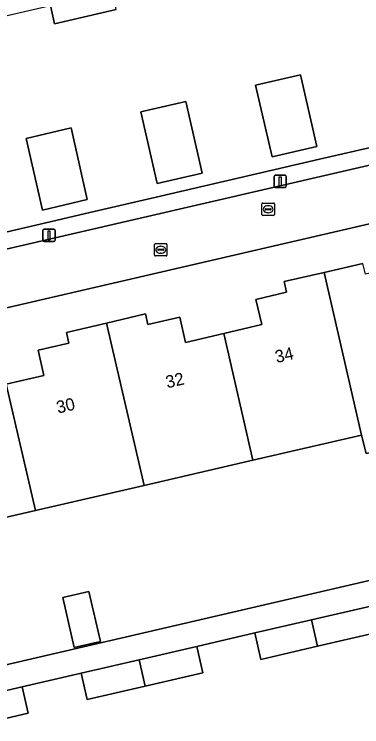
# Model space of a CAD drawing. Extents: x 156412 to 157779, y 382335 to 383768.
# Drawn here: x 156851.9 to 156880, y 382867.3 to 382924.7 of the extents above; entities that cross this region are included whole.
import ezdxf

# ---------------------------------------------------------------- set-up
doc = ezdxf.new("R2010")
doc.units = 0
for name, color, linetype in [('IMGEO_Erf', 7, 'Continuous'), ('IMGEO_Lichtmast', 7, 'Continuous'), ('IMGEO_Pand', 7, 'Continuous'), ('IMGEO_Pand_nummerreeks', 7, 'Continuous'), ('IMGEO_Rijbaan_lokaal_open', 7, 'Continuous'), ('IMGEO_Rioolput', 7, 'Continuous'), ('IMGEO_Voetpad_open', 7, 'Continuous')]:
    doc.layers.add(name, color=color, linetype=linetype)

msp = doc.modelspace()

# ---------------------------------------------------------------- linework, layer by layer
at = {"layer": 'IMGEO_Erf'}
for points in [[(156848.818, 382906.551), (156854.483, 382907.865), (156858.036, 382908.689), (156863.737, 382910.012), (156867.334, 382910.846), (156873.002, 382912.161), (156876.57, 382912.989), (156882.212, 382914.297), (156885.799, 382915.13), (156891.499, 382916.452), (156895.055, 382917.277), (156900.75, 382918.598), (156904.344, 382919.432), (156910.004, 382920.745), (156910.196, 382920.789), (156909.964, 382921.799), (156906.351, 382937.287)], [(156860.182, 382925.052), (156855.207, 382923.901), (156854.865, 382925.381)], [(156911.516, 382914.937), (156840.966, 382898.64)], [(156851.293, 382894.869), (156854.347, 382895.564), (156853.883, 382897.602), (156856.359, 382898.166), (156856.164, 382899.024), (156859.401, 382899.793), (156862.527, 382900.536), (156862.726, 382899.678), (156865.298, 382900.275), (156865.771, 382898.239), (156868.843, 382898.952), (156871.917, 382899.666), (156871.445, 382901.702), (156873.919, 382902.276), (156873.72, 382903.133), (156876.942, 382903.871), (156880.083, 382904.591)], [(156913.547, 382884.574), (156908.775, 382883.472), (156909.267, 382881.341), (156904.481, 382880.236), (156899.936, 382879.187), (156899.445, 382881.317), (156894.749, 382880.232), (156895.241, 382878.103), (156890.456, 382876.998), (156885.891, 382875.944), (156885.399, 382878.073), (156880.705, 382876.988), (156881.196, 382874.86), (156876.422, 382873.758), (156871.846, 382872.702), (156871.355, 382874.829), (156866.68, 382873.749), (156867.171, 382871.622), (156862.516, 382870.547), (156857.84, 382869.468), (156857.35, 382871.594), (156852.577, 382870.491), (156853.068, 382868.367), (156848.333, 382867.271)]]:
    msp.add_lwpolyline(points, dxfattribs=at)
for points in [[(156875.048, 382919.794), (156876.346, 382914.009), (156872.743, 382913.177), (156871.419, 382918.95)], [(156865.796, 382917.655), (156867.12, 382911.876), (156863.472, 382911.031), (156862.163, 382916.808)], [(156857.839, 382909.739), (156854.23, 382908.894), (156852.908, 382914.667), (156856.533, 382915.514)], [(156915.255, 382898.9), (156906.295, 382896.833), (156907.108, 382893.323), (156898.239, 382891.277), (156897.771, 382893.297), (156892.783, 382892.146), (156892.439, 382893.637), (156888.737, 382892.783), (156885.006, 382891.922), (156885.35, 382890.431), (156880.343, 382889.276), (156879.97, 382890.76), (156871.201, 382888.741), (156862.433, 382886.721), (156853.655, 382884.699), (156844.666, 382882.629), (156847.325, 382871.335), (156903.057, 382884.256), (156902.503, 382886.644), (156905.282, 382887.29), (156905.837, 382884.902), (156917.831, 382887.65)], [(156855.858, 382877.69), (156857.969, 382878.178), (156858.9, 382874.15), (156856.789, 382873.662)]]:
    msp.add_lwpolyline(points, close=True, dxfattribs=at)
at = {"layer": 'IMGEO_Lichtmast'}
for p, q in [((156872.907, 382910.813), (156872.907, 382911.613)), ((156872.907, 382911.613), (156872.907, 382910.813)), ((156873.007, 382911.713), (156873.797, 382911.713)), ((156873.797, 382911.713), (156873.007, 382911.713)), ((156873.897, 382911.613), (156873.897, 382910.813)), ((156873.897, 382910.813), (156873.897, 382911.613)), ((156873.797, 382910.713), (156873.007, 382910.713)), ((156873.007, 382910.713), (156873.797, 382910.713)), ((156854.252, 382906.461), (156854.252, 382907.261)), ((156854.252, 382907.261), (156854.252, 382906.461)), ((156854.352, 382907.361), (156855.142, 382907.361)), ((156855.142, 382907.361), (156854.352, 382907.361)), ((156855.242, 382907.261), (156855.242, 382906.461)), ((156855.242, 382906.461), (156855.242, 382907.261)), ((156855.142, 382906.361), (156854.352, 382906.361)), ((156854.352, 382906.361), (156855.142, 382906.361))]:
    msp.add_line(p, q, dxfattribs=at)
for points in [[(156873.327, 382911.588), (156873.477, 382911.588), (156873.477, 382910.838), (156873.327, 382910.838), (156873.327, 382911.588)], [(156854.672, 382907.236), (156854.822, 382907.236), (156854.822, 382906.486), (156854.672, 382906.486), (156854.672, 382907.236)]]:
    msp.add_lwpolyline(points, dxfattribs=at)
for centre, start, end in [((156873.007, 382911.613), 90, 180), ((156873.007, 382911.613), 90, 180), ((156873.797, 382911.613), 0, 90), ((156873.797, 382911.613), 360, 90), ((156873.007, 382910.813), 180, 270), ((156873.007, 382910.813), 180, 270), ((156873.797, 382910.813), 270, 0), ((156873.797, 382910.813), 270, 0), ((156854.352, 382907.261), 90, 180), ((156854.352, 382907.261), 90, 180), ((156855.142, 382907.261), 0, 90), ((156855.142, 382907.261), 360, 90), ((156854.352, 382906.461), 180, 270), ((156854.352, 382906.461), 180, 270), ((156855.142, 382906.461), 270, 0), ((156855.142, 382906.461), 270, 0)]:
    msp.add_arc(centre, 0.1, start, end, dxfattribs=at)
at = {"layer": 'IMGEO_Pand'}
for points in [[(156849.094, 382931.86), (156848.925, 382931.821), (156850.649, 382924.406), (156854.865, 382925.381), (156855.207, 382923.901), (156860.182, 382925.052), (156859.889, 382926.543), (156858.17, 382933.954), (156858.331, 382933.991), (156857.442, 382937.845), (156857.276, 382937.806), (156854.131, 382937.073), (156854.325, 382936.236), (156851.769, 382935.646), (156852.463, 382932.637)], [(156872.743, 382913.177), (156876.346, 382914.009), (156875.048, 382919.794), (156871.419, 382918.95)], [(156867.12, 382911.876), (156865.796, 382917.655), (156862.163, 382916.808), (156863.472, 382911.031)], [(156857.839, 382909.739), (156856.533, 382915.514), (156852.908, 382914.667), (156854.23, 382908.894)], [(156879.97, 382890.76), (156880.343, 382889.276), (156885.35, 382890.431), (156885.006, 382891.922), (156888.737, 382892.783), (156886.384, 382902.993), (156883.322, 382902.288), (156882.853, 382904.325), (156880.28, 382903.733), (156880.083, 382904.591), (156876.942, 382903.871)], [(156879.97, 382890.76), (156876.942, 382903.871), (156873.72, 382903.133), (156873.919, 382902.276), (156871.445, 382901.702), (156871.917, 382899.666), (156868.843, 382898.952), (156871.201, 382888.741)], [(156859.401, 382899.793), (156862.433, 382886.721), (156871.201, 382888.741), (156868.843, 382898.952), (156865.771, 382898.239), (156865.298, 382900.275), (156862.726, 382899.678), (156862.527, 382900.536)], [(156853.655, 382884.699), (156862.433, 382886.721), (156859.401, 382899.793), (156856.164, 382899.024), (156856.359, 382898.166), (156853.883, 382897.602), (156854.347, 382895.564), (156851.293, 382894.869)], [(156853.655, 382884.699), (156851.293, 382894.869), (156848.194, 382894.163), (156847.73, 382896.201), (156845.156, 382895.615), (156844.961, 382896.473), (156841.641, 382895.717), (156844.666, 382882.629)], [(156855.858, 382877.69), (156856.789, 382873.662), (156858.9, 382874.15), (156857.969, 382878.178)], [(156875.927, 382875.885), (156876.422, 382873.758), (156881.196, 382874.86), (156880.705, 382876.988)], [(156875.927, 382875.885), (156871.355, 382874.829), (156871.846, 382872.702), (156876.422, 382873.758)], [(156862.516, 382870.547), (156867.171, 382871.622), (156866.68, 382873.749), (156862.024, 382872.674)], [(156862.516, 382870.547), (156862.024, 382872.674), (156857.35, 382871.594), (156857.84, 382869.468)], [(156847.84, 382869.397), (156848.333, 382867.271), (156853.068, 382868.367), (156852.577, 382870.491)]]:
    msp.add_lwpolyline(points, close=True, dxfattribs=at)
at = {"layer": 'IMGEO_Rijbaan_lokaal_open'}
msp.add_lwpolyline([(156837.115, 382897.607), (156838.598, 382897.917), (156840.966, 382898.64), (156911.516, 382914.937), (156910.626, 382918.883), (156910.514, 382919.415), (156764.262, 382885.667), (156691.253, 382868.836), (156691.37, 382868.246), (156689.34, 382868.448), (156683.638, 382869.423)], dxfattribs=at)
at = {"layer": 'IMGEO_Rioolput'}
for p, q in [((156871.933, 382908.538), (156871.933, 382909.39)), ((156872.008, 382909.464), (156872.86, 382909.464)), ((156872.192, 382908.958), (156872.192, 382908.97)), ((156872.63, 382908.921), (156872.232, 382908.921)), ((156872.235, 382909.007), (156872.633, 382909.007)), ((156872.421, 382909.244), (156872.446, 382909.244)), ((156872.676, 382908.97), (156872.676, 382908.958)), ((156872.934, 382909.39), (156872.934, 382908.538)), ((156872.86, 382908.464), (156872.008, 382908.464)), ((156872.444, 382908.684), (156872.419, 382908.684)), ((156863.267, 382905.274), (156863.267, 382906.126)), ((156863.342, 382906.2), (156864.194, 382906.2)), ((156864.268, 382906.126), (156864.268, 382905.274)), ((156863.526, 382905.694), (156863.526, 382905.706)), ((156863.964, 382905.657), (156863.566, 382905.657)), ((156863.569, 382905.743), (156863.967, 382905.743)), ((156863.755, 382905.98), (156863.78, 382905.98)), ((156864.01, 382905.706), (156864.01, 382905.694)), ((156864.194, 382905.2), (156863.342, 382905.2)), ((156863.778, 382905.42), (156863.753, 382905.42))]:
    msp.add_line(p, q, dxfattribs=at)
for points in [[(156871.933, 382908.538), (156871.933, 382909.39)], [(156872.008, 382909.464), (156872.86, 382909.464)], [(156872.934, 382909.39), (156872.934, 382908.538)], [(156872.86, 382908.464), (156872.008, 382908.464)], [(156863.267, 382905.274), (156863.267, 382906.126)], [(156863.342, 382906.2), (156864.194, 382906.2)], [(156864.268, 382906.126), (156864.268, 382905.274)], [(156864.194, 382905.2), (156863.342, 382905.2)]]:
    msp.add_lwpolyline(points, dxfattribs=at)
for centre, radius, start, end in [((156872.01, 382909.388), 0.0765, 91.55205, 178.44795), ((156872.01, 382909.388), 0.0765, 91.55205, 178.44795), ((156872.232, 382908.967), 0.0403, 85.87752, 175.75265), ((156872.229, 382908.957), 0.0366, 178.93798, 274.71019), ((156872.633, 382908.964), 0.043, 264.86636, 352.45326), ((156872.637, 382908.969), 0.0386, 1.73085, 96.63898), ((156872.858, 382909.388), 0.0765, 1.55205, 88.44795), ((156872.858, 382909.388), 0.0765, 1.55205, 88.44795), ((156872.01, 382908.54), 0.0765, 181.55205, 268.44795), ((156872.01, 382908.54), 0.0765, 181.55205, 268.44795), ((156872.858, 382908.54), 0.0765, 271.55205, 358.44795), ((156872.858, 382908.54), 0.0765, 271.55205, 358.44795), ((156863.344, 382906.124), 0.0765, 91.55205, 178.44795), ((156863.344, 382906.124), 0.0765, 91.55205, 178.44795), ((156864.192, 382906.124), 0.0765, 1.55205, 88.44795), ((156864.192, 382906.124), 0.0765, 1.55205, 88.44795), ((156863.566, 382905.703), 0.0403, 85.87752, 175.75265), ((156863.563, 382905.693), 0.0366, 178.93798, 274.71019), ((156863.967, 382905.7), 0.043, 264.86636, 352.45326), ((156863.971, 382905.705), 0.0386, 1.73085, 96.63898), ((156863.344, 382905.276), 0.0765, 181.55205, 268.44795), ((156863.344, 382905.276), 0.0765, 181.55205, 268.44795), ((156864.192, 382905.276), 0.0765, 271.55205, 358.44795), ((156864.192, 382905.276), 0.0765, 271.55205, 358.44795)]:
    msp.add_arc(centre, radius, start, end, dxfattribs=at)
for centre, major_axis, ratio, start_param, end_param in [((156872.42, 382908.964), (-0.387, 0.002), 0.722429, 4.712389, 7.853982), ((156872.445, 382908.964), (-0.39, 0.002), 0.717154, 1.570796, 4.712389), ((156863.754, 382905.7), (-0.387, 0.002), 0.722429, 4.712389, 7.853982), ((156863.779, 382905.7), (-0.39, 0.002), 0.717154, 1.570796, 4.712389)]:
    msp.add_ellipse(centre, major_axis=major_axis, ratio=ratio, start_param=start_param, end_param=end_param, dxfattribs=at)
at = {"layer": 'IMGEO_Voetpad_open'}
msp.add_lwpolyline([(156764.262, 382885.667), (156910.514, 382919.415), (156910.196, 382920.789), (156910.004, 382920.745), (156904.344, 382919.432), (156900.75, 382918.598), (156895.055, 382917.277), (156891.499, 382916.452), (156885.799, 382915.13), (156882.212, 382914.297), (156876.57, 382912.989), (156873.002, 382912.161), (156867.334, 382910.846), (156863.737, 382910.012), (156858.036, 382908.689), (156854.483, 382907.865), (156848.818, 382906.551)], dxfattribs=at)
msp.add_lwpolyline([(156885.399, 382878.073), (156889.962, 382879.127), (156894.749, 382880.232), (156899.445, 382881.317), (156903.986, 382882.366), (156908.775, 382883.472), (156913.547, 382884.574), (156918.253, 382885.661), (156917.831, 382887.65), (156905.837, 382884.902), (156903.057, 382884.256), (156847.325, 382871.335), (156847.84, 382869.397), (156852.577, 382870.491), (156857.35, 382871.594), (156862.024, 382872.674), (156866.68, 382873.749), (156871.355, 382874.829), (156875.927, 382875.885), (156880.705, 382876.988)], close=True, dxfattribs=at)

# ---------------------------------------------------------------- texts
at = {"layer": 'IMGEO_Pand_nummerreeks'}
for s, p in [('34', (156873.115, 382896.572)), ('32', (156864.291, 382894.534)), ('30', (156855.477, 382892.497))]:
    msp.add_text(s, height=1, rotation=13.00489, dxfattribs=at).set_placement(p)

doc.saveas('drawing.dxf')
